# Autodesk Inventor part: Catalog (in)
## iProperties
Shininess: 64.0
Length Units: 11272
Angle Units: 11279
Time Units: 11290
Mass Units: 11286
Length Display Precision: 3
Angle Display Precision: 2
Compacted: True
Part Number: Catalog (in)
Document SubType Name: Modeling
Created: 2002-07
Density: 1 g/cm^3
Density: 0.0
Volumn: 0.0
Area: 0.0
PropertySet Name: Model Information
Control State: 0
Master: False
Checked Out: False
